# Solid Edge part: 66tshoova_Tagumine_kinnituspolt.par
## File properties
Author: KULL
Template: Iso Metric Part.par
Last saved by: KULL
Revision: 9
Application: Solid Edge
Accuracy: 0,990
Face Style: Model Default
Fill Style: Normal
Coef. of Thermal Exp: 0.0
Thermal Conductivity: 0.0
Specific Heat: 0.0
Modulus of Elasticity: 0.0
Poisson's Ratio: 0.0
Yield Stress: 0.0
Ultimate Stress: 0.0
Elongation: 0.0
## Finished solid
Body 1: solid body, 9 faces, 8 edges, 0 vertices.
  Faces by surface: plane 4, cylinder 3, torus 2
  Edges by curve: circle 8
Bounding box of the edges (mm; curved faces can reach further): 56.000 x 7.000 x 7.000, from (-28, 41.5, 53.311) to (28, 48.5, 60.311).
Cylindrical faces by radius (mm): R2.5 x1, R3.5 x2
Toroidal faces (ring radius, tube radius in mm): R2.5 r1 x2
Planar faces by outward normal: +x 2, -x 2
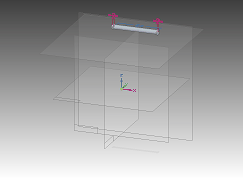
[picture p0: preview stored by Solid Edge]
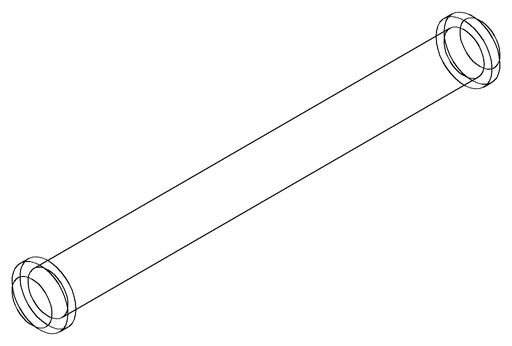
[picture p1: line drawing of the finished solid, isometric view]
